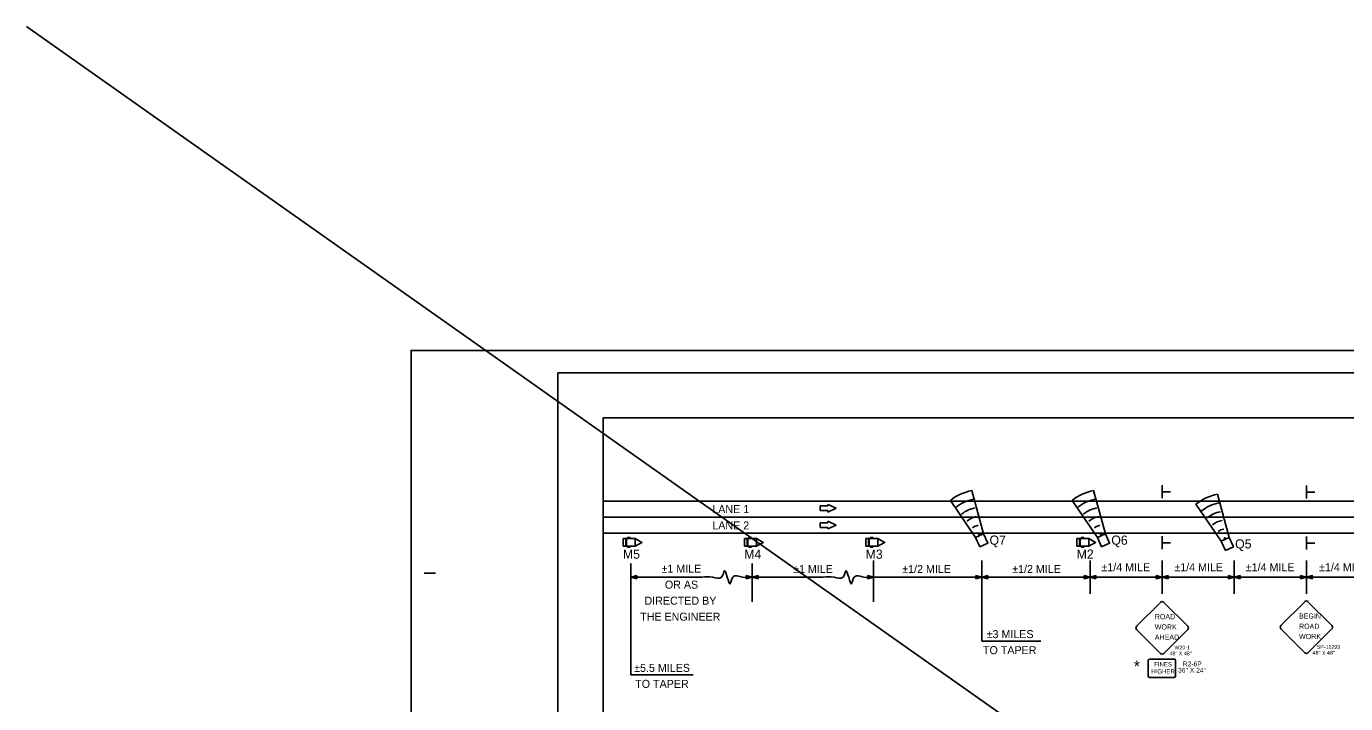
# Model space of a CAD drawing. Extents: x 1379436 to 1387057, y 792703 to 795604.
# Drawn here: x 1379436 to 1381631, y 794294 to 795422 of the extents above; entities that cross this region are included whole.
import ezdxf

# ---------------------------------------------------------------- set-up
doc = ezdxf.new("R2010")
doc.units = 0
for name, color, linetype in [('Black Area Fill Shapes', 7, 'Continuous'), ('Default', 7, 'Continuous'), ('DEV BORDER CELL', 7, 'Continuous'), ('DEV BREAKLINE TYPE 2 CELL', 7, 'Continuous'), ('DEV CMS PLAN VIEW CELL', 7, 'Continuous'), ('DEV DIRECTION OF TRAFFIC FLOW ARROW CELL', 7, 'Continuous'), ('DEV LINE TERMINATOR TYPE 3 CELL', 7, 'Continuous'), ('Prop Mkg Skp Wht', 7, 'Continuous'), ('Prop Mkg Solid White Lane Line', 7, 'Continuous'), ('Prop Mkg Solid Yellow Edge Line', 7, 'Continuous'), ('RS R2-1E CELL', 7, 'Continuous'), ('RS R5-1A CELL', 7, 'Continuous'), ('Scratch_Level_0', 7, 'Continuous'), ('Sheet Plot Border Outside CELL', 7, 'Continuous'), ('TCP Linework', 7, 'Continuous'), ('Text', 7, 'Continuous'), ('WS W20-5R CELL', 7, 'Continuous')]:
    doc.layers.add(name, color=color, linetype=linetype)

msp = doc.modelspace()

# ---------------------------------------------------------------- linework, layer by layer
at = {"layer": 'Black Area Fill Shapes'}
for points in [[(1381022.6, 794555.2), (1381015.5, 794570.7), (1381028.8, 794576.8), (1381035.9, 794561.3)], [(1381225.2, 794555.2), (1381218.1, 794570.7), (1381231.4, 794576.8), (1381238.5, 794561.3)], [(1381431.2, 794548.9), (1381424, 794564.5), (1381437.3, 794570.6), (1381444.5, 794555)]]:
    msp.add_lwpolyline(points, close=True, dxfattribs=at)
at = {"layer": 'Default'}
for p, q in [((1379436.3, 795421.7), (1382883.5, 792987.4)), ((1381025.9, 794532.3), (1381025.9, 794476.8)), ((1381205.9, 794532.3), (1381205.9, 794476.8)), ((1381325.9, 794532.3), (1381325.9, 794476.8)), ((1381445.9, 794532.3), (1381445.9, 794476.8)), ((1381565.9, 794532.3), (1381565.9, 794476.8)), ((1380441.9, 794504.5), (1380559.9, 794504.5)), ((1380845.9, 794504.5), (1382495.8, 794504.5))]:
    msp.add_line(p, q, dxfattribs=at)
at = {"layer": 'DEV BORDER CELL'}
for p, q in [((1380322.2, 794844.7), (1380322.2, 794844.7)), ((1380098, 794511), (1380116.7, 794511))]:
    msp.add_line(p, q, dxfattribs=at)
msp.add_lwpolyline([(1382570.8, 794844.7), (1380320.7, 794844.7), (1380320.7, 793269.7), (1382570.8, 793269.7)], close=True, dxfattribs=at)
at = {"layer": 'DEV BREAKLINE TYPE 2 CELL'}
for points in [[(1380643.9, 794504.5), (1380627.8, 794504.5), (1380611.5, 794504.5), (1380606.9, 794493.4), (1380597.8, 794515.1), (1380593, 794504.5), (1380578.3, 794504.5), (1380559.9, 794504.5)], [(1380845.9, 794504.5), (1380829.8, 794504.5), (1380813.5, 794504.5), (1380808.9, 794493.4), (1380799.8, 794515.1), (1380795, 794504.5), (1380780.2, 794504.5), (1380761.9, 794504.5)]]:
    msp.add_spline(points, degree=3, dxfattribs=at)
at = {"layer": 'DEV CMS PLAN VIEW CELL'}
for p, q in [((1380429, 794569), (1380449, 794569)), ((1380429, 794556.1), (1380429, 794569)), ((1380429, 794569), (1380429, 794556.1)), ((1380433.7, 794556.1), (1380433.7, 794569)), ((1380434.8, 794556.1), (1380434.8, 794569)), ((1380436.6, 794570.6), (1380440.7, 794570.6)), ((1380436.6, 794569.4), (1380440.7, 794569.4)), ((1380449, 794556.1), (1380449, 794569)), ((1380449, 794569), (1380460.2, 794562.5)), ((1380449, 794556.1), (1380460.2, 794562.5)), ((1380630.9, 794569), (1380650.9, 794569)), ((1380630.9, 794556.1), (1380630.9, 794569)), ((1380630.9, 794569), (1380630.9, 794556.1)), ((1380635.6, 794556.1), (1380635.6, 794569)), ((1380636.6, 794556.1), (1380636.6, 794569)), ((1380638.4, 794570.6), (1380642.6, 794570.6)), ((1380638.4, 794569.4), (1380642.6, 794569.4)), ((1380650.9, 794556.1), (1380650.9, 794569)), ((1380650.9, 794569), (1380662.1, 794562.5)), ((1380650.9, 794556.1), (1380662.1, 794562.5)), ((1380832.9, 794569), (1380852.9, 794569)), ((1380832.9, 794556.1), (1380832.9, 794569)), ((1380832.9, 794569), (1380832.9, 794556.1)), ((1380837.5, 794556.1), (1380837.5, 794569)), ((1380838.6, 794556.1), (1380838.6, 794569)), ((1380840.4, 794570.6), (1380844.5, 794570.6)), ((1380840.4, 794569.4), (1380844.5, 794569.4)), ((1380852.9, 794556.1), (1380852.9, 794569)), ((1380852.9, 794569), (1380864.1, 794562.5)), ((1380852.9, 794556.1), (1380864.1, 794562.5)), ((1381183.9, 794569), (1381203.9, 794569)), ((1381183.9, 794556.1), (1381183.9, 794569)), ((1381183.9, 794569), (1381183.9, 794556.1)), ((1381188.6, 794556.1), (1381188.6, 794569)), ((1381189.7, 794556.1), (1381189.7, 794569)), ((1381191.5, 794570.6), (1381195.6, 794570.6)), ((1381191.5, 794569.4), (1381195.6, 794569.4)), ((1381203.9, 794556.1), (1381203.9, 794569)), ((1381203.9, 794569), (1381215.1, 794562.5)), ((1381203.9, 794556.1), (1381215.1, 794562.5)), ((1380429, 794556.1), (1380449, 794556.1)), ((1380436.6, 794555.8), (1380440.7, 794555.8)), ((1380436.6, 794554.7), (1380440.7, 794554.7)), ((1380630.9, 794556.1), (1380650.9, 794556.1)), ((1380638.4, 794555.8), (1380642.6, 794555.8)), ((1380638.4, 794554.7), (1380642.6, 794554.7)), ((1380832.9, 794556.1), (1380852.9, 794556.1)), ((1380840.4, 794555.8), (1380844.5, 794555.8)), ((1380840.4, 794554.7), (1380844.5, 794554.7)), ((1381183.9, 794556.1), (1381203.9, 794556.1)), ((1381191.5, 794555.8), (1381195.6, 794555.8)), ((1381191.5, 794554.7), (1381195.6, 794554.7))]:
    msp.add_line(p, q, dxfattribs=at)
for centre in [(1380460.3, 794562.5), (1380662.2, 794562.5), (1380864.2, 794562.5), (1381215.2, 794562.5)]:
    msp.add_circle(centre, 0.114, dxfattribs=at)
for centre, start, end in [((1380437.3, 794570), 142.0883, 217.9117), ((1380439.9, 794570), 322.0883, 37.9117), ((1380639.2, 794570), 142.0883, 217.9117), ((1380641.8, 794570), 322.0883, 37.9117), ((1380841.2, 794570), 142.0883, 217.9117), ((1380843.8, 794570), 322.0883, 37.9117), ((1381192.2, 794570), 142.0883, 217.9117), ((1381194.9, 794570), 322.0883, 37.9117), ((1380437.3, 794555.2), 142.0883, 217.9117), ((1380439.9, 794555.2), 322.0883, 37.9117), ((1380639.2, 794555.2), 142.0883, 217.9117), ((1380641.8, 794555.2), 322.0883, 37.9117), ((1380841.2, 794555.2), 142.0883, 217.9117), ((1380843.8, 794555.2), 322.0883, 37.9117), ((1381192.2, 794555.2), 142.0883, 217.9117), ((1381194.9, 794555.2), 322.0883, 37.9117)]:
    msp.add_arc(centre, 0.954, start, end, dxfattribs=at)
at = {"layer": 'DEV DIRECTION OF TRAFFIC FLOW ARROW CELL'}
for p, q in [((1380783.7, 794619.2), (1380769.9, 794625.7)), ((1380769.9, 794625.7), (1380769.9, 794623.1)), ((1380769.9, 794623.1), (1380757.1, 794623.1)), ((1380757.1, 794623.1), (1380757.1, 794615.4)), ((1380757.1, 794615.4), (1380769.9, 794615.4)), ((1380769.9, 794612.8), (1380783.7, 794619.2)), ((1380769.9, 794615.4), (1380769.9, 794612.8)), ((1380769.9, 794595.2), (1380757.1, 794595.2)), ((1380757.1, 794595.2), (1380757.1, 794587.4)), ((1380757.1, 794587.4), (1380769.9, 794587.4)), ((1380783.7, 794591.3), (1380769.9, 794597.8)), ((1380769.9, 794597.8), (1380769.9, 794595.2)), ((1380769.9, 794584.8), (1380783.7, 794591.3)), ((1380769.9, 794587.4), (1380769.9, 794584.8))]:
    msp.add_line(p, q, dxfattribs=at)
at = {"layer": 'DEV LINE TERMINATOR TYPE 3 CELL'}
for points in [[(1380452.3, 794501.9), (1380441.9, 794504.5), (1380452.3, 794507.1)], [(1380452.3, 794501.9), (1380441.9, 794504.5), (1380452.3, 794507.1)], [(1380633.5, 794501.9), (1380643.9, 794504.5), (1380633.5, 794507.1)], [(1380633.5, 794501.9), (1380643.9, 794504.5), (1380633.5, 794507.1)], [(1380654.3, 794501.9), (1380643.9, 794504.5), (1380654.3, 794507.1)], [(1380654.3, 794501.9), (1380643.9, 794504.5), (1380654.3, 794507.1)], [(1380835.5, 794501.9), (1380845.9, 794504.5), (1380835.5, 794507.1)], [(1380835.5, 794501.9), (1380845.9, 794504.5), (1380835.5, 794507.1)], [(1381015.5, 794501.9), (1381025.9, 794504.5), (1381015.5, 794507.1)], [(1381015.5, 794501.9), (1381025.9, 794504.5), (1381015.5, 794507.1)], [(1381036.3, 794501.9), (1381025.9, 794504.5), (1381036.3, 794507.1)], [(1381036.3, 794501.9), (1381025.9, 794504.5), (1381036.3, 794507.1)], [(1381195.5, 794501.9), (1381205.9, 794504.5), (1381195.5, 794507.1)], [(1381195.5, 794501.9), (1381205.9, 794504.5), (1381195.5, 794507.1)], [(1381216.3, 794501.9), (1381205.9, 794504.5), (1381216.3, 794507.1)], [(1381216.3, 794501.9), (1381205.9, 794504.5), (1381216.3, 794507.1)], [(1381315.5, 794501.9), (1381325.9, 794504.5), (1381315.5, 794507.1)], [(1381315.5, 794501.9), (1381325.9, 794504.5), (1381315.5, 794507.1)], [(1381336.3, 794501.9), (1381325.9, 794504.5), (1381336.3, 794507.1)], [(1381336.3, 794501.9), (1381325.9, 794504.5), (1381336.3, 794507.1)], [(1381435.5, 794501.9), (1381445.9, 794504.5), (1381435.5, 794507.1)], [(1381435.5, 794501.9), (1381445.9, 794504.5), (1381435.5, 794507.1)], [(1381456.3, 794501.9), (1381445.9, 794504.5), (1381456.3, 794507.1)], [(1381456.3, 794501.9), (1381445.9, 794504.5), (1381456.3, 794507.1)], [(1381555.5, 794501.9), (1381565.9, 794504.5), (1381555.5, 794507.1)], [(1381555.5, 794501.9), (1381565.9, 794504.5), (1381555.5, 794507.1)], [(1381576.3, 794501.9), (1381565.9, 794504.5), (1381576.3, 794507.1)], [(1381576.3, 794501.9), (1381565.9, 794504.5), (1381576.3, 794507.1)]]:
    msp.add_lwpolyline(points, dxfattribs=at)
for centre, start, end in [((1380454.6, 794504.5), 131.3264, 228.6736), ((1380454.6, 794504.5), 131.3264, 228.6736), ((1380631.2, 794504.5), 311.3264, 48.6736), ((1380631.2, 794504.5), 311.3264, 48.6736), ((1380656.6, 794504.5), 131.3264, 228.6736), ((1380656.6, 794504.5), 131.3264, 228.6736), ((1380833.2, 794504.5), 311.3264, 48.6736), ((1380833.2, 794504.5), 311.3264, 48.6736), ((1381013.2, 794504.5), 311.3264, 48.6736), ((1381013.2, 794504.5), 311.3264, 48.6736), ((1381038.6, 794504.5), 131.3264, 228.6736), ((1381038.6, 794504.5), 131.3264, 228.6736), ((1381193.2, 794504.5), 311.3264, 48.6736), ((1381193.2, 794504.5), 311.3264, 48.6736), ((1381218.6, 794504.5), 131.3264, 228.6736), ((1381218.6, 794504.5), 131.3264, 228.6736), ((1381313.2, 794504.5), 311.3264, 48.6736), ((1381313.2, 794504.5), 311.3264, 48.6736), ((1381338.6, 794504.5), 131.3264, 228.6736), ((1381338.6, 794504.5), 131.3264, 228.6736), ((1381433.2, 794504.5), 311.3264, 48.6736), ((1381433.2, 794504.5), 311.3264, 48.6736), ((1381458.6, 794504.5), 131.3264, 228.6736), ((1381458.6, 794504.5), 131.3264, 228.6736), ((1381553.2, 794504.5), 311.3264, 48.6736), ((1381553.2, 794504.5), 311.3264, 48.6736), ((1381578.6, 794504.5), 131.3264, 228.6736), ((1381578.6, 794504.5), 131.3264, 228.6736)]:
    msp.add_arc(centre, 3.46, start, end, dxfattribs=at)
at = {"layer": 'Prop Mkg Skp Wht'}
for p, q in [((1380395.7, 794604.5), (1381406.4, 794604.5)), ((1381406.4, 794604.5), (1382495.8, 794604.5))]:
    msp.add_line(p, q, dxfattribs=at)
at = {"layer": 'Prop Mkg Solid White Lane Line'}
for p, q in [((1380395.7, 794577.9), (1381406.4, 794577.8)), ((1381406.4, 794577.9), (1382495.8, 794577.9))]:
    msp.add_line(p, q, dxfattribs=at)
at = {"layer": 'Prop Mkg Solid Yellow Edge Line'}
for p, q in [((1380395.7, 794631.1), (1381406.4, 794631.1)), ((1381406.4, 794631.1), (1382495.8, 794631.1))]:
    msp.add_line(p, q, dxfattribs=at)
at = {"layer": 'RS R2-1E CELL'}
for p, q in [((1381305.5, 794368), (1381345.7, 794368)), ((1381305.5, 794337.7), (1381345.7, 794337.7))]:
    msp.add_line(p, q, dxfattribs=at)
for points in [[(1381302.9, 794339.4), (1381302.9, 794366.2)], [(1381348.3, 794366.2), (1381348.3, 794339.4)]]:
    msp.add_lwpolyline(points, dxfattribs=at)
for centre, major_axis, start_param, end_param in [((1381305.5, 794366.2), (-2.65, 0), 4.712162, 6.283185), ((1381345.7, 794366.2), (2.65, 0), 0, 1.570796), ((1381305.5, 794339.4), (-2.65, 0), 0, 1.570796), ((1381345.7, 794339.4), (-2.65, 0), 1.570796, 3.141593)]:
    msp.add_ellipse(centre, major_axis=major_axis, ratio=0.666667, start_param=start_param, end_param=end_param, dxfattribs=at)
at = {"layer": 'Scratch_Level_0'}
msp.add_lwpolyline([(1382495.8, 794769.7), (1380395.7, 794769.7), (1380395.7, 793344.7), (1381714, 793344.7), (1381714, 793522.1), (1382495.8, 793522.1)], close=True, dxfattribs=at)
at = {"layer": 'Sheet Plot Border Outside CELL'}
msp.add_lwpolyline([(1380076.3, 793232.2), (1382608.3, 793232.2), (1382608.3, 794882.2), (1380076.3, 794882.2)], close=True, dxfattribs=at)
at = {"layer": 'TCP Linework'}
for p, q in [((1381325.9, 794657.6), (1381325.9, 794636)), ((1381325.9, 794646.7), (1381339.9, 794646.7)), ((1381565.9, 794657.1), (1381565.9, 794635.6)), ((1381565.9, 794646.2), (1381579.9, 794646.2)), ((1381325.9, 794572.7), (1381325.9, 794551.2)), ((1381325.9, 794561.9), (1381339.9, 794561.9)), ((1381565.9, 794572.3), (1381565.9, 794550.7)), ((1381565.9, 794561.4), (1381579.9, 794561.4))]:
    msp.add_line(p, q, dxfattribs=at)
at = {"layer": 'Text'}
for p, q in [((1381028.8, 794576.8), (1381009.1, 794648.7)), ((1381231.4, 794576.8), (1381211.7, 794648.7)), ((1381015.5, 794570.7), (1380973.6, 794632.4)), ((1381218.1, 794570.7), (1381176.2, 794632.4)), ((1381424, 794564.5), (1381382.1, 794626.1)), ((1381437.3, 794570.6), (1381417.7, 794642.5)), ((1380441.9, 794527.4), (1380441.9, 794341.8)), ((1380643.9, 794527.4), (1380643.9, 794463.7)), ((1380845.9, 794532.3), (1380845.9, 794476.8)), ((1380845.9, 794527.4), (1380845.9, 794463.7)), ((1381025.9, 794532.3), (1381025.9, 794397.9)), ((1380643.9, 794504.5), (1380761.9, 794504.5)), ((1381025.9, 794397.9), (1381123.8, 794397.9)), ((1380441.9, 794341.8), (1380545.7, 794341.8))]:
    msp.add_line(p, q, dxfattribs=at)
for centre, radius in [((1381023.6, 794570.6), 79.4), ((1381226.2, 794570.6), 79.4), ((1381023.6, 794570.6), 64.7), ((1381226.2, 794570.6), 64.7), ((1381432.1, 794564.4), 79.4), ((1381432.1, 794564.4), 64.7), ((1381023.6, 794570.6), 50), ((1381023.6, 794570.6), 35.3), ((1381226.2, 794570.6), 50), ((1381226.2, 794570.6), 35.3), ((1381432.1, 794564.4), 50), ((1381023.6, 794570.6), 20.6), ((1381226.2, 794570.6), 20.6), ((1381432.1, 794564.4), 35.3), ((1381432.1, 794564.4), 20.6), ((1381023.6, 794570.6), 5.93), ((1381226.2, 794570.6), 5.93), ((1381432.1, 794564.4), 5.93)]:
    msp.add_arc(centre, radius, 100.4731, 129.0092, dxfattribs=at)
at = {"layer": 'WS W20-5R CELL'}
for p, q in [((1381368.4, 794417.4), (1381328.5, 794377.5)), ((1381608.4, 794418.5), (1381568.5, 794378.6))]:
    msp.add_line(p, q, dxfattribs=at)
for points in [[(1381283.3, 794422.7), (1381323.3, 794462.6)], [(1381328.5, 794462.6), (1381368.4, 794422.7)], [(1381523.3, 794423.8), (1381563.3, 794463.7)], [(1381568.5, 794463.7), (1381608.4, 794423.8)], [(1381323.3, 794377.5), (1381283.3, 794417.4)], [(1381563.3, 794378.6), (1381523.3, 794418.5)]]:
    msp.add_lwpolyline(points, dxfattribs=at)
for centre, start, end in [((1381325.9, 794460), 89.9935, 135), ((1381325.9, 794460), 44.987, 89.9935), ((1381565.9, 794461.1), 89.9935, 135), ((1381565.9, 794461.1), 44.987, 89.9935), ((1381286, 794420.1), 135, 225), ((1381365.8, 794420.1), 315, 45), ((1381526, 794421.2), 135, 225), ((1381605.8, 794421.2), 315, 45), ((1381325.9, 794380.2), 225, 270), ((1381325.9, 794380.2), 270, 315), ((1381565.9, 794381.2), 225, 270), ((1381565.9, 794381.2), 270, 315)]:
    msp.add_arc(centre, 3.73, start, end, dxfattribs=at)

# ---------------------------------------------------------------- texts
at = {"layer": 'Default'}
msp.add_text('*', height=19.7, dxfattribs=at).set_placement((1381278.8, 794346.3))
at = {"layer": 'RS R5-1A CELL'}
for s, p in [('FINES', (1381312.7, 794355.8)), ('HIGHER', (1381307.9, 794344.1))]:
    msp.add_text(s, height=7.27, dxfattribs=at).set_placement(p)
at = {"layer": 'Text'}
for s, height, p in [('LANE 1', 13.31, (1380577.5, 794611.2)), ('LANE 2', 13.31, (1380577.5, 794584)), ('Q7', 15.29, (1381038.7, 794558.5)), ('Q6', 15.29, (1381241.3, 794558.5)), ('Q5', 15.29, (1381447.3, 794552.3)), ('M5', 15.29, (1380428.7, 794535.2)), ('M4', 15.29, (1380630.6, 794535.2)), ('M3', 15.29, (1380832.5, 794535.2)), ('M2', 15.29, (1381183.6, 794535.2)), ('±1 MILE', 13.31, (1380493, 794512)), ('±1 MILE', 13.31, (1380711.8, 794511.4)), ('±1/2 MILE', 13.31, (1380893.5, 794511.4)), ('±1/2 MILE', 13.31, (1381076.4, 794511.4)), ('±1/4 MILE', 13.31, (1381224.9, 794514.4)), ('±1/4 MILE', 13.31, (1381346.2, 794514.4)), ('±1/4 MILE', 13.31, (1381465, 794514.4)), ('±1/4 MILE', 13.31, (1381587, 794514.4)), ('OR AS ', 13.31, (1380498.6, 794485.4)), ('DIRECTED BY ', 13.31, (1380464.6, 794458.7)), ('THE ENGINEER', 13.31, (1380457.4, 794432.1)), ('±3 MILES ', 13.31, (1381033.9, 794403)), ('TO TAPER', 13.31, (1381027.8, 794376.3)), ('±5.5 MILES ', 13.31, (1380447.5, 794346.8)), ('TO TAPER', 13.31, (1380449.2, 794320.2))]:
    msp.add_text(s, height=height, dxfattribs=at).set_placement(p)
at = {"layer": 'WS W20-5R CELL'}
for s, height, p in [('ROAD', 8.52, (1381313.6, 794434.5)), ('BEGIN', 8.52, (1381553.6, 794435.5)), ('ROAD', 8.52, (1381553.6, 794418.5)), ('AHEAD', 8.52, (1381313.6, 794400.4)), ('WORK', 8.52, (1381313.6, 794417.4)), ('WORK', 8.52, (1381553.6, 794401.5)), ('W20-1', 6.39, (1381346.3, 794384.2)), ('SP-11299', 6.39, (1381583, 794385.2)), ("48'' X 48''", 6.389, (1381338.1, 794374.3)), ('R2-6P', 8.02, (1381360.4, 794356.1)), ("48'' X 48''", 6.389, (1381576.1, 794375.4)), ("36'' X 24''", 8.016, (1381352.4, 794345.5))]:
    msp.add_text(s, height=height, dxfattribs=at).set_placement(p)

doc.saveas('drawing.dxf')
